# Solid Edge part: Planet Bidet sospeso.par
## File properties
Title: Planet Bidet sospeso
Author: DESYS
Template: Normal.par
Last saved by: s.pallini
Revision: 42
Application: Solid Edge
Tipo di contenuto documento: 0
Precisione: 0,990
Document Number: 8106
Revision: 0
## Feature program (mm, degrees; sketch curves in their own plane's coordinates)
lofted protrusion "unnamed LoftedProtrusion 1"
sketch for "unnamed Protrusion 1" plane through (0, 0, 410) normal (0, 0, 1) x-axis (1, 0, 0)
  line (-281.006, -125) -> (-156.1249, -125)
  line (-281.006, 125) -> (-281.006, -125)
  line (-281.006, 125) -> (-156.1249, 125)
  dimension (linear) = 281.006
extrude "unnamed Protrusion 1" add to key point along -normal
sketch for "unnamed Cutout 1" plane through (0, 0, 0) normal (0, -1, 0) x-axis (1, 0, 0)
  line (-281.006, 410) -> (211.175, 360)
extrude "unnamed Cutout 1" cut through
lofted cutout "unnamed LoftedCutout 1"
lofted cutout "unnamed LoftedCutout 2"
lofted cutout "unnamed LoftedCutout 3"
sketch for "unnamed Cutout 2" plane through (0, 0, 0) normal (0, -1, 0) x-axis (1, 0, 0)
  line (-261.006, 30) -> (-261.006, -23.5209)
  line (-281.006, 30) -> (-261.006, 30)
  line (-281.006, 300) -> (-281.006, 30)
  line (-281.006, 300) -> (-262.6938, 300)
  line (-262.6938, 300) -> (-262.6938, 386.9393)
  line (-262.6938, 386.9393) -> (-184.5389, 386.9393)
  arc centre (128.9588, 378.5087) radius 313.611 from (-184.5389, 386.9393) to (-95.4684, 159.4555) ccw
  line (-95.4684, 159.4555) -> (-95.4684, 0)
  dimension (linear) = 281.006
  dimension (linear) = 281.006
extrude "unnamed Cutout 2" cut finite 210 symmetric
sketch for "unnamed Cutout 3" plane through (0, 0, 0) normal (0, 0, 1) x-axis (1, 0, 0)
  line (-95.4684, -105) -> (8.5066, -95.764)
  arc centre (-2.9504, 0) radius 96.4469 from (8.5066, 95.764) to (8.5066, -95.764) cw
  line (-95.4684, 105) -> (8.5066, 95.764)
  line (-95.4684, 105) -> (-95.4684, -105)
extrude "unnamed Cutout 3" cut to key point along +normal
sketch for "Foro_1" plane through (-23.798, 0.5154, 410) normal (0, 0, 1) x-axis (1, 0, 0)
  hole centre (-192.2081, -0.5154) bore radius 17.5
hole "Foro_1" through  Plane_Distance = 410 mm
pattern "unnamed Pattern 1" of "Foro_1"
fillet "Rotondo_14" radius 2
fillet "Rotondo_16" radius 8
sketch for "ExtrudedProtrusion_7" plane through (-51.0057, 0, 159.4555) normal (0, 0, -1) x-axis (-0.996078, -0.088481, 0)
  arc centre (848.79, 768.4564) radius 1099.2977 from (-187.0831, 400.4585) to (-86.006, 190) ccw
extrude "ExtrudedProtrusion_7" add finite 40 along +normal
sketch for "Foro_3" plane through (-51.006, 0, 119.4555) normal (0, 0, -1) x-axis (1, 0, 0)
  hole centre (-10, 0) bore radius 25
hole "Foro_3" finite
sketch for "ExtrudedProtrusion_8" plane through (0, 0, 0) normal (0, -1, 0) x-axis (1, 0, 0)
extrude "ExtrudedProtrusion_8" add finite 40 symmetric
fillet "Rotondo_17" radius 20
fillet "Rotondo_18" radius 10
fillet "Rotondo_19" radius 7
fillet "Rotondo_20" radius 5
fillet "Rotondo_21" radius 20
fillet "Rotondo_22" radius 20
fillet "Rotondo_24" radius 5
fillet "Rotondo_25" radius 10
fillet "Rotondo_26" radius 5
sketch for "ExtrudedProtrusion_9" plane through (-281.006, 0, 204.4547) normal (-1, 0, 0) x-axis (0, -1, 0)
extrude "ExtrudedProtrusion_9" add finite 20 along -normal
fillet "Rotondo_28" radius 20
sketch for "Foro_4" plane through (0, 0, 0) normal (1, 0, 0) x-axis (0, 1, 0)
hole "Foro_4" finite
sketch for "unnamed Cutout 4" plane through (0, 0, 0) normal (0, -1, 0) x-axis (1, 0, 0)
extrude "unnamed Cutout 4" cut through
sketch for "ExtrudedProtrusion_10" plane through (-281.006, 0, 262.9298) normal (-1, 0, 0) x-axis (0, -1, 0)
extrude "ExtrudedProtrusion_10" add finite 20 along -normal
fillet "Rotondo_30" radius 50
fillet "Rotondo_31" radius 5
fillet "Rotondo_32" radius 5
fillet "Rotondo_34" radius 3
fillet "Rotondo_35" radius 5
sketch for "Foro_5" plane through (-281.006, 0, 266.2326) normal (-1, 0, 0) x-axis (0, -1, 0)
  hole centre (92.5, 33.7674) bore radius 12.5
hole "Foro_5" diameter 25 through
sketch for "unnamed Hole 1" plane through (-281.006, 0, 266.2326) normal (-1, 0, 0) x-axis (0, -1, 0)
hole "unnamed Hole 1" through
pattern "unnamed Pattern 2" of "Foro_5", "unnamed Hole 1"
fillet "Rotondo_36" radius 60
fillet "Rotondo_37" radius 10
fillet "Rotondo_38" radius 8
fillet "Rotondo_40" radius 7
fillet "Rotondo_41" radius 7
fillet "Rotondo_42" radius 8
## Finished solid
Body 1: solid body, 128 faces, 301 edges, 172 vertices.
  Faces by surface: cylinder 50, blend 35, plane 21, torus 14, sphere 7, spline 1
  Edges by curve: circle 106, line 94, intersection 64, ellipse 37
Bounding box of the edges (mm; curved faces can reach further): 508.677 x 436.918 x 370.973, from (-281.006, -218.4597, 37.9598) to (227.6713, 218.4578, 408.9326).
Cylindrical faces by radius (mm): R3 x10, R5 x13, R7 x7, R10 x6, R12.5 x2, R17.5 x1, R20 x4, R25 x1, R35 x1, R50 x2, R96.4469 x1, R313.611 x2
Toroidal faces (ring radius, tube radius in mm): R-85.5357 r333.9736 x1, R25 r5 x2, R30 r5 x1, R40 r5 x1, R40 r20 x2, R55 r5 x2, R76.4469 r20 x1, R318.611 r5 x2, R333.611 r20 x2
Spherical faces by radius (mm): R5 x5, R10 x2
Planar faces by outward normal: +x 2, +y 3, -x 1, -y 3, -z 4, oblique 8
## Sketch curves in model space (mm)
closed spline through (6.747, 195.7275, 380.7676), (200.5771, 0, 361.0766), (6.747, -195.7275, 380.7676), (-187.0831, 0, 400.4585)
arc centre (848.79, 0, 768.4564) radius 1099.2977 from (-187.0831, 0, 400.4585) through (-142.1476, 0, 292.5383) to (-86.006, 0, 190)
arc centre (-71.2892, 0, 487.9179) radius 300 from (-36.006, 0, 190) through (104.5005, 0, 244.8171) to (200.5771, 0, 361.0766)
circle centre (-61.006, 0, 190) radius 25
circle centre (9.7167, 0, 410) radius 175.7275
arc centre (-85.5357, 0, 236.7726) radius 333.9736 from (200, 0, 410) through (244.6709, 0, 186.7528) to (150, 0, 0)
circle centre (0, 0, 410) radius 200
circle centre (0, 0, 0) radius 150
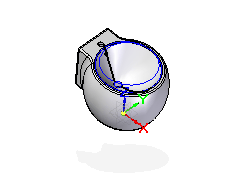
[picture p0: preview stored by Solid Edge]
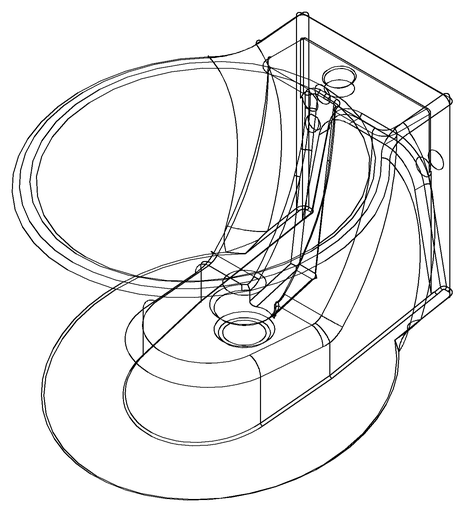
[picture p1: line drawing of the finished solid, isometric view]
